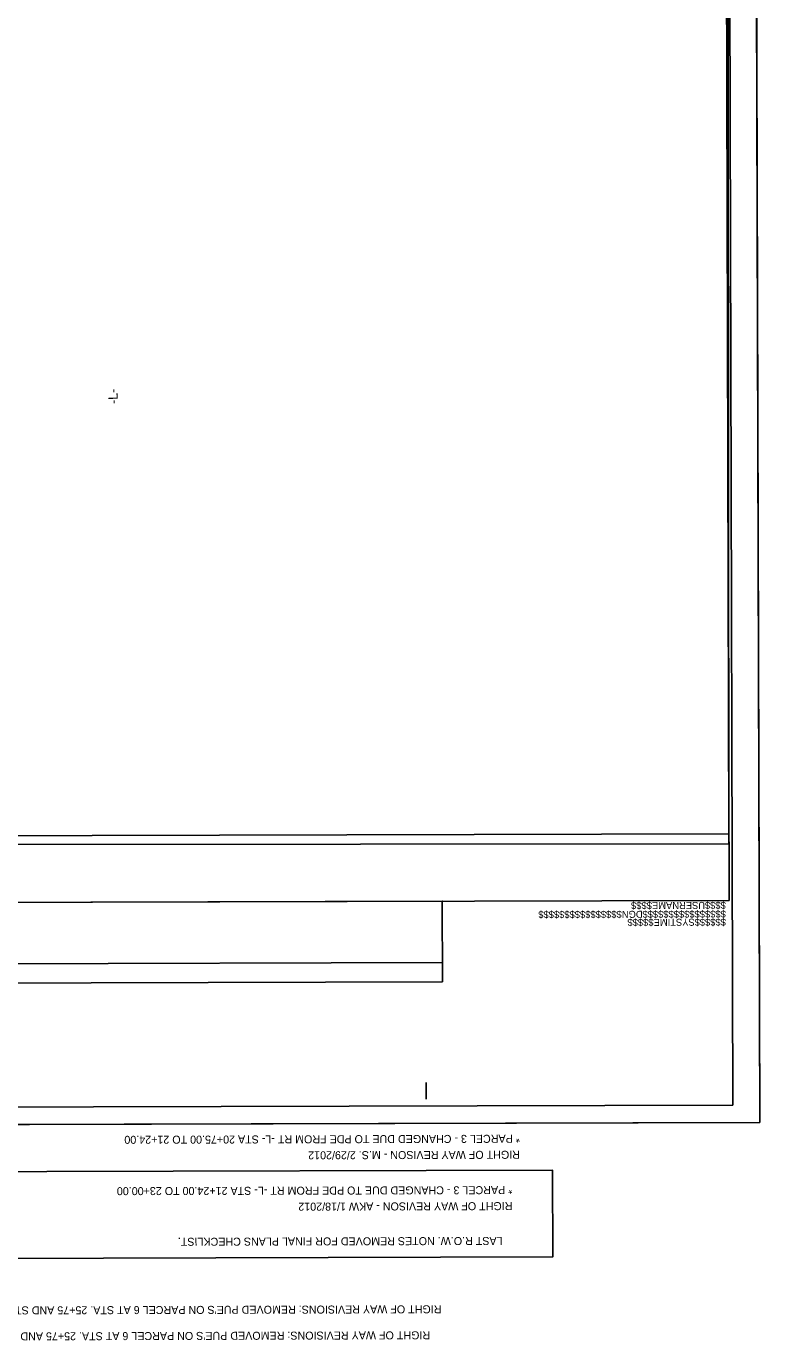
# Model space of a CAD drawing. Extents: x 1373110 to 1374209, y 550682 to 552749.
# Drawn here: x 1373659 to 1374209, y 550682 to 551668 of the extents above; entities that cross this region are included whole.
import ezdxf

# ---------------------------------------------------------------- set-up
doc = ezdxf.new("R2010")
doc.units = 0
for name, color, linetype in [('Prop Drainage Structure Drop Inlet Grate 2 Narrow Slots and Flat Grates 840 29 TB Label', 7, 'Continuous'), ('Prop Drainage Structure Gutter Shoulder Berm Label', 7, 'Continuous'), ('Prop Drainage Structure Pipe Alternate 18in', 7, 'Continuous'), ('Prop Drainage Structure Pipe CSP 15in Label', 7, 'Continuous'), ('Prop Drainage Structure Pipe RCP 15in Class IV Label', 7, 'Continuous'), ('Prop Drainage Structure Retain Label', 7, 'Continuous'), ('Prop Drainage Structure Tops and Inverts LABEL', 7, 'Continuous'), ('Prop Earthen Structure Base Ditch Special Lateral with Rip Rap Detail Label', 7, 'Continuous'), ('Prop Earthen Structure Base Ditch with Rip Rap Detail CELL', 7, 'Continuous'), ('Prop Erosion Rip Rap Class B Label', 7, 'Continuous')]:
    doc.layers.add(name, color=color, linetype=linetype)

msp = doc.modelspace()

# ---------------------------------------------------------------- linework, layer by layer
at = {"layer": 'Prop Drainage Structure Drop Inlet Grate 2 Narrow Slots and Flat Grates 840 29 TB Label'}
for p, q in [((1374186.2, 551012.6), (1374186.2, 551012.6)), ((1373959.12, 550863.5), (1373959.1, 550876))]:
    msp.add_line(p, q, dxfattribs=at)
for points in [[(1373132.1, 552509.76), (1373136.2, 551009.73), (1374186.2, 551012.6), (1374182.1, 552512.6)], [(1374186.2, 551012.6), (1373136.23, 551009.7), (1373132.64, 552309.68), (1373282.7, 552310.11), (1373282.16, 552510.14), (1374182.1, 552512.6)]]:
    msp.add_lwpolyline(points, close=True, dxfattribs=at)
at = {"layer": 'Prop Drainage Structure Gutter Shoulder Berm Label'}
msp.add_lwpolyline([(1374209.17, 550846.17), (1374204.56, 552529.67), (1373109.57, 552526.67), (1373114.17, 550843.18)], close=True, dxfattribs=at)
at = {"layer": 'Prop Drainage Structure Pipe Alternate 18in'}
msp.add_lwpolyline([(1373295.71, 550743.21), (1373295.54, 550808.28), (1374053.81, 550810.35), (1374053.99, 550745.28)], close=True, dxfattribs=at)
at = {"layer": 'Prop Drainage Structure Pipe CSP 15in Label'}
for p, q in [((1374209.17, 550846.17), (1374204.56, 552529.67)), ((1373114.17, 550843.18), (1374209.17, 550846.17))]:
    msp.add_line(p, q, dxfattribs=at)
at = {"layer": 'Prop Drainage Structure Pipe RCP 15in Class IV Label'}
msp.add_lwpolyline([(1373136.23, 551009.7), (1374186.2, 551012.6), (1374182.1, 552512.59), (1373343.59, 552510.3), (1373344.24, 552271.05), (1373132.76, 552270.47)], close=True, dxfattribs=at)
at = {"layer": 'Prop Drainage Structure Tops and Inverts LABEL'}
msp.add_lwpolyline([(1374189.13, 550859.12), (1374184.56, 552525.1), (1373129.58, 552522.23), (1373134.14, 550856.23)], close=True, dxfattribs=at)
at = {"layer": 'Prop Earthen Structure Base Ditch Special Lateral with Rip Rap Detail Label'}
msp.add_line((1373971.33, 550966.03), (1373180.69, 550963.86), dxfattribs=at)
msp.add_lwpolyline([(1373971.39, 550951.48), (1373180.75, 550949.32), (1373180.55, 551009.86), (1373971.2, 551012.02)], close=True, dxfattribs=at)
at = {"layer": 'Prop Earthen Structure Base Ditch with Rip Rap Detail CELL'}
msp.add_lwpolyline([(1374186.06, 551062.6), (1374182.23, 552462.6), (1373343.73, 552460.31), (1373344.24, 552271.05), (1373132.76, 552270.47), (1373136.07, 551059.72)], close=True, dxfattribs=at)
at = {"layer": 'Prop Erosion Rip Rap Class B Label'}
for points in [[(1374186.06, 551062.6), (1374182.23, 552462.6), (1373343.73, 552460.31), (1373344.24, 552271.05), (1373132.76, 552270.47), (1373136.07, 551059.72)], [(1374186.13, 551055.1), (1374185.31, 551891.66), (1374039.33, 551891.53), (1374038.82, 552461.52), (1373346.29, 552460.9), (1373346.46, 552271.64), (1373134.97, 552271.45), (1373135.76, 551468.67), (1373357.23, 551468.89), (1373357.64, 551054.29)]]:
    msp.add_lwpolyline(points, close=True, dxfattribs=at)

# ---------------------------------------------------------------- texts
at = {"layer": 'Prop Drainage Structure Drop Inlet Grate 2 Narrow Slots and Flat Grates 840 29 TB Label'}
for s, p in [('$$$$USERNAME$$$$', (1374183.83, 551011.5)), ('$$$$$$$$$$$$$$$$DGN$$$$$$$$$$$$$$$$', (1374183.86, 551004.95)), ('$$$$$$SYSTIME$$$$$', (1374183.9, 550998.88))]:
    msp.add_text(s, height=5.25, rotation=180.15673, dxfattribs=at).set_placement(p)
at = {"layer": 'Prop Drainage Structure Pipe Alternate 18in'}
for s, p in [('* PARCEL 3 - CHANGED DUE TO PDE FROM RT -L- STA 20+75.00 TO 21+24.00', (1374029.38, 550836.9)), ('RIGHT OF WAY REVISON - M.S. 2/29/2012', (1374029.41, 550824.9)), ('* PARCEL 3 - CHANGED DUE TO PDE FROM RT -L- STA 21+24.00 TO 23+00.00', (1374023.75, 550798.39)), ('RIGHT OF WAY REVISON - AKW 1/18/2012', (1374023.79, 550786.39))]:
    msp.add_text(s, height=6, rotation=180.15672, dxfattribs=at).set_placement(p)
at = {"layer": 'Prop Drainage Structure Retain Label'}
msp.add_text('-L-', height=7, rotation=92.24194, dxfattribs=at).set_placement((1373728.03, 551384.89))
at = {"layer": 'Prop Earthen Structure Base Ditch Special Lateral with Rip Rap Detail Label'}
for s, p in [('LAST R.O.W. NOTES REMOVED FOR FINAL PLANS CHECKLIST.', (1374016.39, 550760.29)), ("RIGHT OF WAY REVISIONS: REMOVED PUE'S ON PARCEL 6 AT STA. 25+75 AND STA. 27+20.  REVISED EASEMENT LINE AT STA. 25+89.  10/17/11   NKB", (1373970.57, 550709.05)), ("RIGHT OF WAY REVISIONS: REMOVED PUE'S ON PARCEL 6 AT STA. 25+75 AND STA. 27+20.  REVISED EASEMENT LINE AT STA. 25+89.  10/17/11   NKB", (1373962.08, 550689.54))]:
    msp.add_text(s, height=6, rotation=180.15672, dxfattribs=at).set_placement(p)

doc.saveas('drawing.dxf')
